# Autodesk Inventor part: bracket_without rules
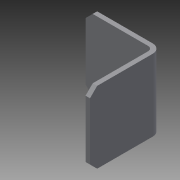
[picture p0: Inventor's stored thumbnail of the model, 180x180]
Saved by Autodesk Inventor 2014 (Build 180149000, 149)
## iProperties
Created: 2007-08
Part Number: bracket_without rules
Document SubType Name: Modeling
Designer: DaveR
Density: 1 g/cm^3
Mass: 7.59456 g
Surface Area: 56.7093 cm^2
Volume: 7.59456 cm^3
Material: Generic
Appearance: Default
Author: DaveR
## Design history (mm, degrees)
sketch "Sketch1"
  geometry: L1 (-3.311, 44.86)-(-3.311, -5.94); L2 (-3.311, -5.94)-(47.489, -5.94); L3 (47.489, -5.94)-(47.489, -2.765); L4 (47.489, -2.765)-(-0.136, -2.765); L5 (-0.136, -2.765)-(-0.136, 44.86); L6 (-0.136, 44.86)-(-3.311, 44.86)
  constraints: 12 end point, 2 parallel, 2 perpendicular, 1 vertical
  dimensions: "base_thickness" = 3.175 distance of L2.end L3.end; "flange_thickness" = 3.175 distance of L5.end L1.start; "base_length" = 50.8 distance of L1.end L2.end; "flange_height" = 50.8 distance of L1.start L1.end
extrude "main_body" new body sketch "Sketch1" taper "draft_dont_use" = 0 deg; stored distance "bracket_width" = 50.8
chamfer "Chamfers" distance "chamfer" = 5.08; stored, may be unused: second distance "d25" = 3.175, angle "d26" = 45 deg
hole "base_hole" diameter "base_hole_dia" = 6.35; stored, may be unused: countersink angle "d12" = 82 deg, drill point angle "d14" = 118 deg; dims "d9" = 12.7, "d10" = 9.525, "d11" = 6.35, "d13" = 19.05, "base_hole_width_loc" = 25.4 (= 0.5 x bracket_width), "base_hole_length_loc" = 15.875 (computed from base_length)
pattern_linear "base_hole_pattern" dims "spacing_between_base_holes" = 19.05 (= 0.5 x bracket_width - base_hole_dia)
hole "flange_hole" diameter "flange_hole_dia" = 6.35 (= base_hole_dia); stored, may be unused: countersink angle "d21" = 82 deg, drill point angle "d23" = 118 deg; dims "d18" = 12.7, "d19" = 9.525, "d20" = 6.35, "d22" = 19.05, "flange_hole_width_loc" = 25.4 (= 0.5 x bracket_width), "flange_hole_length_loc" = 15.875 (computed from flange_height)
pattern_linear "flange_hole_pattern" dims "spacing_between_flange_holes" = 19.05 (= 0.5 x bracket_width - flange_hole_dia)
fillet "Inside_fillet" dims "inside_rad" = 3.175
fillet "Outside_fillet" dims "outside_rad" = 6.35 (= inside_rad + flange_thickness)
sketch "Sketch2"
  geometry: L1 (-0.136, 9.935)-(12.564, -2.765); L2 (-0.136, 39.78)-(-0.136, 0.41) reference; L3 (3.039, -2.765)-(42.409, -2.765) reference; 2 further points
  constraints: 2 end point, 2 point on line
  dimensions: "rib_angle" = 45 deg angle of L3 L1; "rib_height" = 12.7 distance from line of L3 L1.start
feature "center_rib" sketch "Sketch2" dims "d31" = 2.54, "rib_thickness" = 2.38125 (= 0.75 x flange_thickness), "rib_draft_dont_use" = 0
pattern_linear "rib_pattern" dims "spacing_between_ribs" = 10.31875
body "Solid1"
